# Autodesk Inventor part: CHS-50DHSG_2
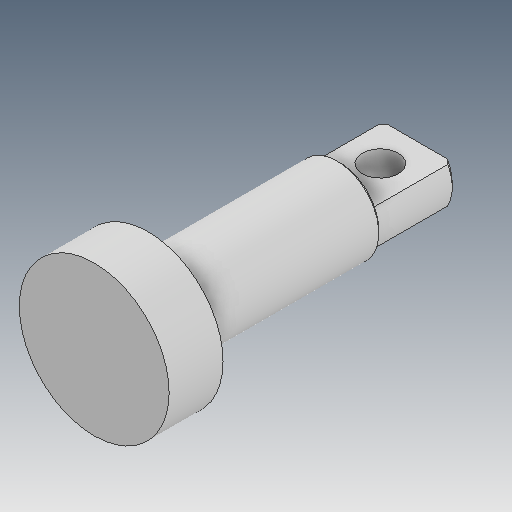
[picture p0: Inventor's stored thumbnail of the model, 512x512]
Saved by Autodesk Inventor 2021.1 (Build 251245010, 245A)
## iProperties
Created: 2019-04
Part Number: CHS-50DHSG_2
Material: Ogólny
Document SubType Name: Modeling
Designer: user
Density: 1 g/cm^3
Appearance: Domyślna
Author: user
Revision Number: ÈÎºÎ
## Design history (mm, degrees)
feature "ÊäÈë1"
node "Bryła1"
